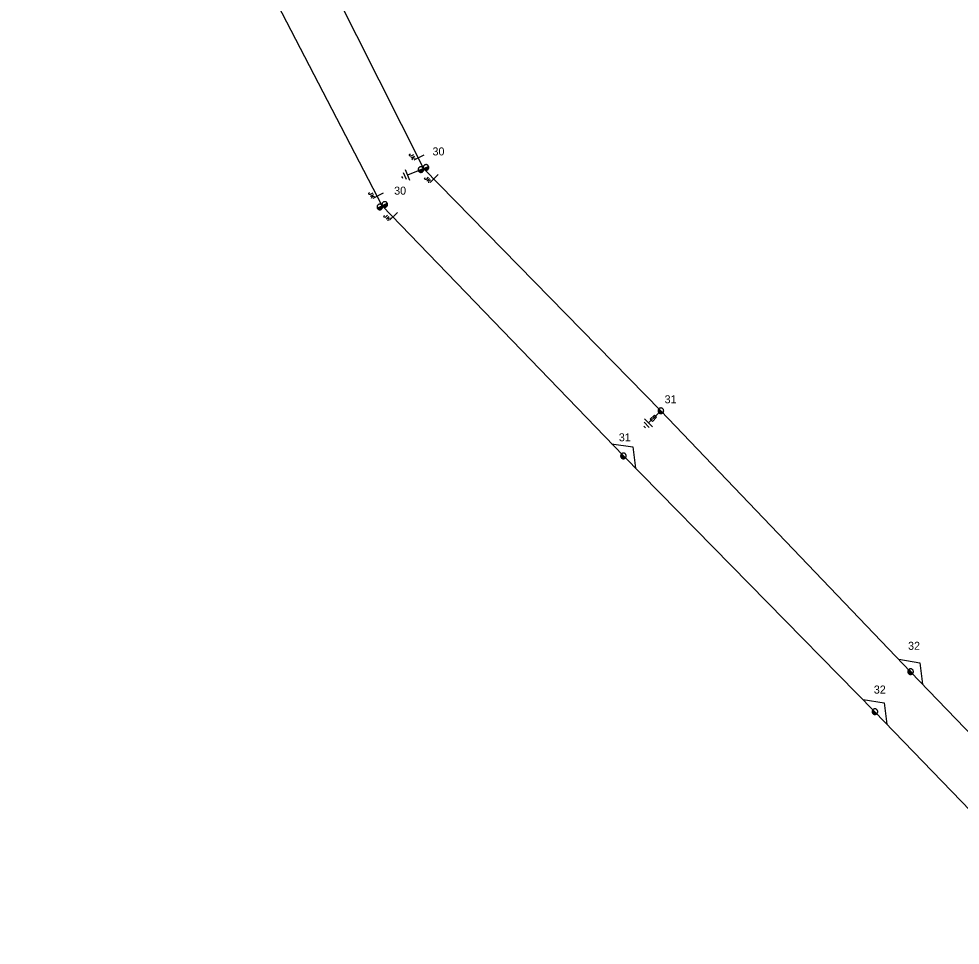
# Model space of a CAD drawing. Extents: x -540340 to -537226, y -1183949 to -1180375.
# Drawn here: x -539155.8 to -538950.1, y -1181553.6 to -1181351.3 of the extents above; entities that cross this region are included whole.
import ezdxf

# ---------------------------------------------------------------- set-up
doc = ezdxf.new("R2010")
doc.units = 0
for name, color, linetype in [('Vrstva 1', 7, 'Continuous'), ('Vrstva 13', 7, 'Continuous'), ('Vrstva 14', 7, 'Continuous'), ('Vrstva 15', 7, 'Continuous'), ('Vrstva 16', 7, 'Continuous'), ('Vrstva 18', 7, 'Continuous'), ('Vrstva 2', 7, 'Continuous')]:
    doc.layers.add(name, color=color, linetype=linetype)

# ---------------------------------------------------------------- blocks, each defined once
blk = doc.blocks.new('VN840')
at = {"layer": 'Vrstva 15'}
for points in [[(-0.01, 1.41), (-0.01, -1.09)], [(-1.51, -1.24), (-1.51, -1.15)], [(-1.48, -1.35), (-1.51, -1.24)], [(-1.33, -1.42), (-1.48, -1.35)], [(-1.27, -1.42), (-1.33, -1.42)], [(-1.13, -1.35), (-1.27, -1.42)], [(-1.09, -1.24), (-1.13, -1.35)], [(-1.09, -0.59), (-1.09, -1.24)], [(-0.68, -0.59), (-0.68, -1.42)], [(-0.68, -1.11), (-0.27, -0.59)], [(-0.54, -0.94), (-0.2, -1.42)]]:
    blk.add_lwpolyline(points, dxfattribs=at)
blk = doc.blocks.new('VN860')
at = {"layer": 'Vrstva 15'}
for points in [[(-3.74, 0), (0.01, 2.82)], [(0.01, 2.82), (3.76, 0)]]:
    blk.add_lwpolyline(points, dxfattribs=at)
blk = doc.blocks.new('VN440')
at = {"layer": 'Vrstva 2'}
for points in [[(1.22, 0), (1.21, 0.13), (1.19, 0.25), (1.16, 0.38), (1.11, 0.5), (1.05, 0.61), (0.98, 0.72), (0.9, 0.82), (0.81, 0.91), (0.71, 0.99), (0.6, 1.06), (0.49, 1.12), (0.37, 1.16), (0.25, 1.2), (0.12, 1.22), (-0.01, 1.22), (-0.14, 1.22), (-0.26, 1.2), (-0.39, 1.16), (-0.51, 1.12), (-0.62, 1.06), (-0.73, 0.99), (-0.83, 0.91), (-0.92, 0.82), (-1, 0.72), (-1.07, 0.61), (-1.13, 0.5), (-1.18, 0.38), (-1.21, 0.25), (-1.23, 0.13), (-1.24, 0), (-1.23, -0.13), (-1.21, -0.26), (-1.18, -0.38), (-1.13, -0.5), (-1.07, -0.62), (-1, -0.73), (-0.92, -0.83), (-0.83, -0.92), (-0.73, -1), (-0.62, -1.07), (-0.51, -1.13), (-0.39, -1.17), (-0.26, -1.2), (-0.14, -1.23), (-0.01, -1.23), (0.12, -1.23), (0.25, -1.2), (0.37, -1.17), (0.49, -1.13), (0.6, -1.07), (0.71, -1), (0.81, -0.92), (0.9, -0.83), (0.98, -0.73), (1.05, -0.62), (1.11, -0.5), (1.16, -0.38), (1.19, -0.26), (1.21, -0.13), (1.22, 0)], [(-1.24, 0), (1.22, 0)], [(-1.18, -0.34), (1.1, -0.34)], [(-1.01, -0.63), (0.97, -0.63)], [(-0.74, -0.92), (0.68, -0.92)]]:
    blk.add_lwpolyline(points, dxfattribs=at)
blk = doc.blocks.new('VN820')
at = {"layer": 'Vrstva 13'}
for points in [[(0, 0), (0, -2.1)], [(-0.32, -1.63), (0.34, -1.63)], [(-0.32, -2.95), (-0.32, -1.63)], [(0, -2.1), (-0.12, -1.86)], [(0, -2.1), (0.12, -1.86)], [(0.34, -1.63), (0.34, -2.95)], [(0.34, -2.95), (-0.32, -2.95)], [(0, -2.95), (0, -3.75)]]:
    blk.add_lwpolyline(points, dxfattribs=at)
blk = doc.blocks.new('VN810')
at = {"layer": 'Vrstva 14'}
for points in [[(0, -1.25), (0, -3.75)], [(1.25, -3.75), (-1.25, -3.75)], [(0.77, -4.37), (-0.8, -4.37)], [(0, -5), (-0.25, -5)], [(0.27, -5), (0, -5)]]:
    blk.add_lwpolyline(points, dxfattribs=at)
blk = doc.blocks.new('VN450')
at = {"layer": 'Vrstva 2'}
for points in [[(0, 0), (-0.01, 0.13), (-0.03, 0.25), (-0.06, 0.38), (-0.11, 0.5), (-0.16, 0.61), (-0.23, 0.72), (-0.31, 0.82), (-0.4, 0.91), (-0.5, 0.99), (-0.61, 1.06), (-0.72, 1.11), (-0.84, 1.16), (-0.97, 1.19), (-1.09, 1.21), (-1.22, 1.22), (-1.35, 1.21), (-1.47, 1.19), (-1.59, 1.16), (-1.71, 1.11), (-1.83, 1.06), (-1.93, 0.99), (-2.03, 0.91), (-2.12, 0.82), (-2.2, 0.72), (-2.27, 0.61), (-2.33, 0.5), (-2.38, 0.38), (-2.41, 0.25), (-2.43, 0.13), (-2.44, 0), (-2.43, -0.13), (-2.41, -0.25), (-2.38, -0.38), (-2.33, -0.5), (-2.27, -0.61), (-2.2, -0.72), (-2.12, -0.82), (-2.03, -0.91), (-1.93, -0.99), (-1.83, -1.06), (-1.71, -1.11), (-1.59, -1.16), (-1.47, -1.19), (-1.35, -1.21), (-1.22, -1.22), (-1.09, -1.21), (-0.97, -1.19), (-0.84, -1.16), (-0.72, -1.11), (-0.61, -1.06), (-0.5, -0.99), (-0.4, -0.91), (-0.31, -0.82), (-0.23, -0.72), (-0.16, -0.61), (-0.11, -0.5), (-0.06, -0.38), (-0.03, -0.25), (-0.01, -0.13), (0, 0)], [(-2.44, 0), (2.44, 0)], [(2.44, 0), (2.43, 0.13), (2.41, 0.25), (2.38, 0.38), (2.33, 0.5), (2.27, 0.61), (2.2, 0.72), (2.12, 0.82), (2.03, 0.91), (1.94, 0.99), (1.83, 1.06), (1.71, 1.11), (1.6, 1.16), (1.47, 1.19), (1.35, 1.21), (1.22, 1.22), (1.09, 1.21), (0.97, 1.19), (0.84, 1.16), (0.72, 1.11), (0.61, 1.06), (0.5, 0.99), (0.4, 0.91), (0.31, 0.82), (0.23, 0.72), (0.16, 0.61), (0.11, 0.5), (0.06, 0.38), (0.03, 0.25), (0.01, 0.13), (0, 0), (0.01, -0.13), (0.03, -0.25), (0.06, -0.38), (0.11, -0.5), (0.16, -0.61), (0.23, -0.72), (0.31, -0.82), (0.4, -0.91), (0.5, -0.99), (0.61, -1.06), (0.72, -1.11), (0.84, -1.16), (0.97, -1.19), (1.09, -1.21), (1.22, -1.22), (1.35, -1.21), (1.47, -1.19), (1.6, -1.16), (1.71, -1.11), (1.83, -1.06), (1.94, -0.99), (2.03, -0.91), (2.12, -0.82), (2.2, -0.72), (2.27, -0.61), (2.33, -0.5), (2.38, -0.38), (2.41, -0.25), (2.43, -0.13), (2.44, 0)], [(-2.4, -0.31), (-0.04, -0.31)], [(-2.26, -0.61), (-0.17, -0.61)], [(-2.01, -0.92), (-0.42, -0.92)], [(0.04, -0.31), (2.4, -0.31)], [(0.17, -0.61), (2.27, -0.61)], [(0.42, -0.92), (2.02, -0.92)]]:
    blk.add_lwpolyline(points, dxfattribs=at)

msp = doc.modelspace()

# ---------------------------------------------------------------- linework, layer by layer
at = {"layer": 'Vrstva 1'}
for points in [[(-539146.14, -1181230.44), (-539111.36, -1181296.54), (-539067.4, -1181383.96), (-539015.51, -1181436.9), (-538960.93, -1181493.88), (-538903.36, -1181553.62)], [(-538939.39, -1181533.04), (-538968.73, -1181502.62), (-539023.69, -1181446.75), (-539076.4, -1181392.09), (-539119.1, -1181309.84), (-539155.83, -1181236.81)]]:
    msp.add_lwpolyline(points, dxfattribs=at)

# ---------------------------------------------------------------- block references
at = {"layer": 'Vrstva 13'}
for name, p, xscale, yscale, rotation in [('VN450', (-539067.4, -1181383.96), 0.5, 0.5, 22.59604730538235), ('VN450', (-539076.4, -1181392.09), 0.5, 0.49999999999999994, 26.82880012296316), ('VN440', (-539015.51, -1181436.89), 0.49999999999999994, 0.5000000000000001, -45.57181110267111), ('VN440', (-539023.69, -1181446.75), 0.5000000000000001, 0.5, -46.04066398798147), ('VN440', (-538960.93, -1181493.88), 0.5, 0.5000000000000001, -46.23683604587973), ('VN440', (-538968.73, -1181502.62), 0.5, 0.5, -45.47121661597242)]:
    msp.add_blockref(name, p, dxfattribs=dict(at, xscale=xscale, yscale=yscale, rotation=rotation))
at = {"layer": 'Vrstva 15'}
for p, rotation in [((-539067.4, -1181383.96), -67.15866664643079), ((-539015.51, -1181436.9), -45.57220309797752)]:
    msp.add_blockref('VN810', p, dxfattribs=dict(at, rotation=rotation))
at = {"layer": 'Vrstva 16', "rotation": -45.57220309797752}
msp.add_blockref('VN820', (-539015.51, -1181436.9), dxfattribs=at)
at = {"layer": 'Vrstva 18'}
for name, p, rotation in [('VN840', (-539068.56, -1181381.65), -63.30270560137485), ('VN840', (-539065.16, -1181386.24), -45.572222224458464), ('VN840', (-539077.47, -1181390.03), -62.56480004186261), ('VN840', (-539074.06, -1181394.52), -46.040986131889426), ('VN860', (-539023.69, -1181446.75), -45.47100555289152), ('VN860', (-538960.93, -1181493.88), -46.23702777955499), ('VN860', (-538968.73, -1181502.62), -46.02845562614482)]:
    msp.add_blockref(name, p, dxfattribs=dict(at, rotation=rotation))

# ---------------------------------------------------------------- texts
at = {"layer": 'Vrstva 14'}
for s, p in [('30', (-539065.42, -1181381.1)), ('30', (-539073.8, -1181389.67)), ('31', (-539014.7, -1181435.25)), ('31', (-539024.7, -1181443.55)), ('32', (-538961.49, -1181489.1)), ('32', (-538968.97, -1181498.66))]:
    msp.add_text(s, height=1.75, dxfattribs=at).set_placement(p)

doc.saveas('drawing.dxf')
